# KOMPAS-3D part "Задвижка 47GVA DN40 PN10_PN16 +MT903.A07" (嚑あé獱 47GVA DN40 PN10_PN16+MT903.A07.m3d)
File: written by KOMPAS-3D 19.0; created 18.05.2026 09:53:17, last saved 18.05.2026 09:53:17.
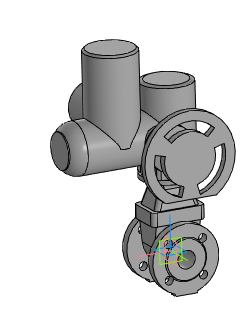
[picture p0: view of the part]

Document properties: Автор: Энергия; Полное имя файла: ..\Задвижка 47GVA DN50_DN1000MT903.A\Задвижка 47GVA DN40 PN10_PN16+MT903.A07.a3d

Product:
- Part/product: Задвижка 47GVA DN40 PN10_PN16 +MT903.A07
    Масса: 80.0859
  - Body: Электропривод МТ903.А07 без блока управления
      Масса: 65.4738
  - Body: Задвижка 47GVA DN40 PN10_PN16 без исполн. мех.
      Масса: 14.612

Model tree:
1. Операция без истории:1
2. Операция без истории:2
